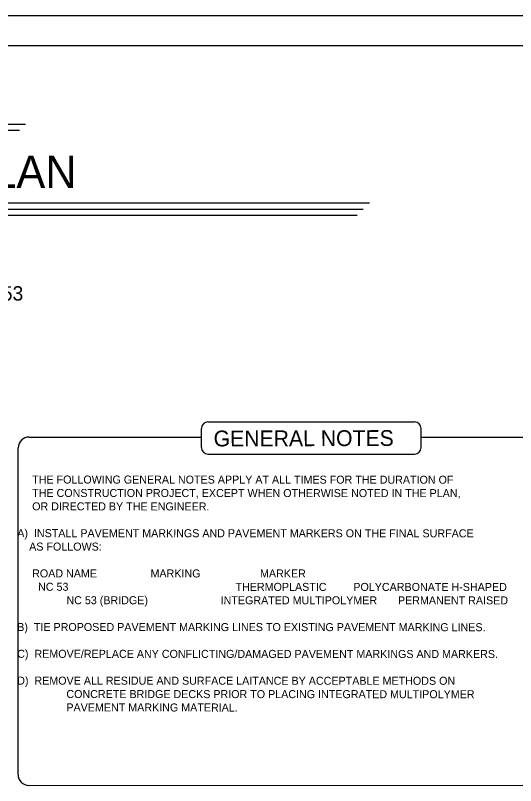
# Model space of a CAD drawing. Extents: x -63 to 3072, y 0 to 1100.
# Drawn here: x 1028 to 1445, y 458 to 1100 of the extents above; entities that cross this region are included whole.
import ezdxf

# ---------------------------------------------------------------- set-up
doc = ezdxf.new("R2010")
doc.units = 0
for name, color, linetype in [('Scratch_Level_0', 7, 'Continuous'), ('Sheet Data Text CELL', 7, 'Continuous'), ('Sheet_Data_Field_CELL', 7, 'Continuous'), ('Sheet_RDY_PE_Seal_Cell', 7, 'Continuous')]:
    doc.layers.add(name, color=color, linetype=linetype)

msp = doc.modelspace()

# ---------------------------------------------------------------- linework, layer by layer
at = {"layer": 'Scratch_Level_0'}
msp.add_line((0, 1100), (1699.98, 1100), dxfattribs=at)
at = {"layer": 'Sheet_RDY_PE_Seal_Cell'}
for p, q in [((38.08, 1074.94), (1651.98, 1074.94)), ((703.65, 1009.37), (1036.4, 1009.38)), ((708.65, 1004.38), (1031.4, 1004.37)), ((417.2, 943.68), (1322.86, 943.68)), ((422.34, 938.54), (1317.72, 938.54)), ((427.48, 933.4), (1312.58, 933.4)), ((1182.93, 739.81), (1182.93, 755.83)), ((1365.96, 739.81), (1365.96, 755.83)), ((1039.46, 748.67), (1182.93, 748.6)), ((1365.97, 748.52), (1513.07, 748.45)), ((1030.2, 467.49), (1030.36, 739.59)), ((1039.28, 458.4), (1513.82, 458.18))]:
    msp.add_line(p, q, dxfattribs=at)
for points in [[(1188.38, 761.29), (1360.51, 761.29)], [(1188.38, 734.36), (1360.51, 734.36)]]:
    msp.add_lwpolyline(points, dxfattribs=at)
for centre, radius, start, end in [((1188.38, 755.83), 5.45, 90, 180), ((1360.51, 755.83), 5.45, 360, 90), ((1039.45, 739.58), 9.09, 89.97341, 179.97341), ((1188.38, 739.81), 5.45, 180, 270), ((1360.51, 739.81), 5.45, 270, 360), ((1039.28, 467.48), 9.09, 179.97341, 269.97341)]:
    msp.add_arc(centre, radius, start, end, dxfattribs=at)

# ---------------------------------------------------------------- texts
at = {"layer": 'Sheet Data Text CELL'}
for s, height, rotation, p in [('PAVEMENT MARKING PLAN', 26.9979, 0.00003, (597.5, 956.21)), ('LOCATION: REPLACE BRIDGE 700037 ON NC 53', 12, 0.12484, (666.21, 861.58)), ('GENERAL NOTES', 13.2, 0.15565, (1193.09, 740.81))]:
    msp.add_text(s, height=height, rotation=rotation, dxfattribs=at).set_placement(p)
at = {"layer": 'Sheet_Data_Field_CELL'}
for s, p in [('            THE FOLLOWING GENERAL NOTES APPLY AT ALL TIMES FOR THE DURATION OF', (1012.2, 709.91)), ('            THE CONSTRUCTION PROJECT, EXCEPT WHEN OTHERWISE NOTED IN THE PLAN,', (1012.2, 698.73)), ('            OR DIRECTED BY THE ENGINEER.', (1012.19, 687.56)), ('       A)  INSTALL PAVEMENT MARKINGS AND PAVEMENT MARKERS ON THE FINAL SURFACE', (1012.18, 665.22)), ('           AS FOLLOWS:', (1012.17, 654.05)), ('            ROAD NAME                  MARKING                    MARKER            ', (1012.16, 631.71)), ('              NC 53', (1012.16, 620.54)), ('     THERMOPLASTIC         POLYCARBONATE H-SHAPED', (1198.94, 620.45)), ('  NC 53 (BRIDGE)', (1065.52, 609.34)), ('INTEGRATED MULTIPOLYMER       PERMANENT RAISED', (1198.94, 609.28)), ('       B)  TIE PROPOSED PAVEMENT MARKING LINES TO EXISTING PAVEMENT MARKING LINES.', (1012.14, 587.03)), ('       C)  REMOVE/REPLACE ANY CONFLICTING/DAMAGED PAVEMENT MARKINGS AND MARKERS.', (1012.13, 564.68)), ('       D)  REMOVE ALL RESIDUE AND SURFACE LAITANCE BY ACCEPTABLE METHODS ON', (1012.12, 542.34)), ('  CONCRETE BRIDGE DECKS PRIOR TO PLACING INTEGRATED MULTIPOLYMER', (1065.48, 531.15)), ('  PAVEMENT MARKING MATERIAL.', (1065.48, 519.98))]:
    msp.add_text(s, height=6.6709, rotation=359.97341, dxfattribs=at).set_placement(p)

doc.saveas('drawing.dxf')
